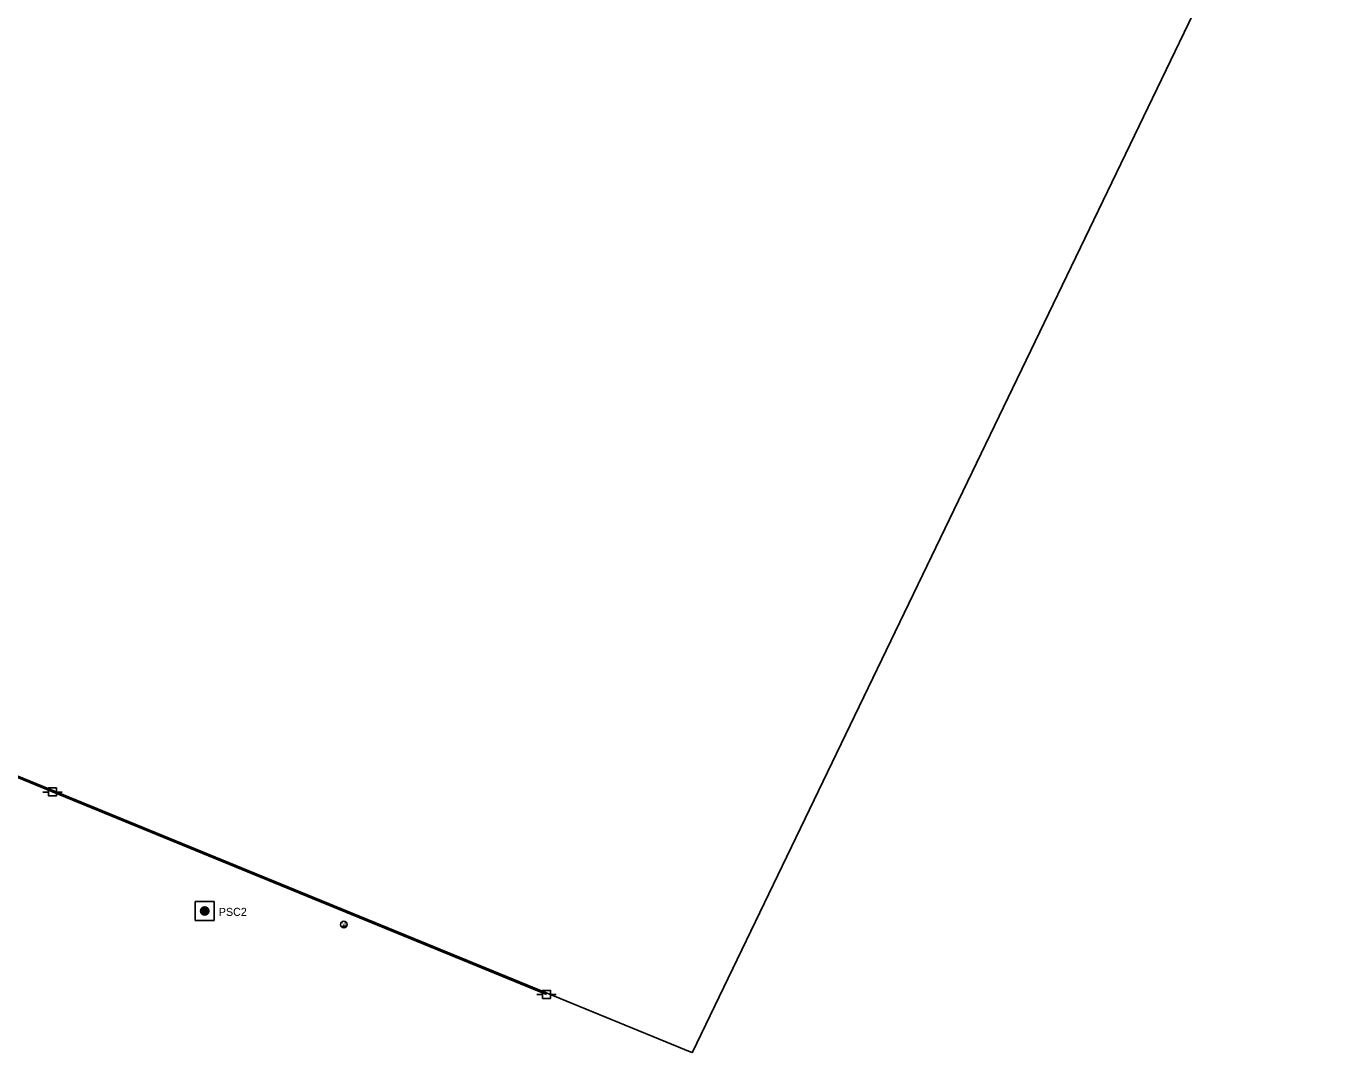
# Model space of a CAD drawing. Extents: x 1903662 to 1907233, y 1108998 to 1112872.
# Drawn here: x 1906248.5 to 1906740.5, y 1109725.4 to 1110110.2 of the extents above; entities that cross this region are included whole.
import ezdxf

# ---------------------------------------------------------------- set-up
doc = ezdxf.new("R2010")
doc.units = 0
for name, color, linetype in [('RD_EX_DV_Prop', 7, 'Continuous'), ('RD_EX_RW', 7, 'Continuous'), ('RD_EX_UT', 7, 'Continuous'), ('RD_HC_Survey', 7, 'Continuous'), ('RD_HC_Survey_txCode', 7, 'Continuous'), ('SV_UT_Electric_Lines', 7, 'Continuous')]:
    doc.layers.add(name, color=color, linetype=linetype)

msp = doc.modelspace()

# ---------------------------------------------------------------- linework, layer by layer
at = {"layer": 'RD_EX_DV_Prop'}
msp.add_lwpolyline([(1906498.14, 1109725.43), (1907232.53, 1111248.36), (1906353.67, 1111725.44)], dxfattribs=at)
at = {"layer": 'RD_EX_RW'}
msp.add_line((1904864.32, 1110395.12), (1906497.97, 1109725.51), dxfattribs=at)
at = {"layer": 'RD_EX_UT'}
for p, q in [((1906254.74, 1109823.13), (1906256.79, 1109823.14)), ((1906258.29, 1109823.17), (1906258.29, 1109823.17)), ((1906259.79, 1109823.14), (1906261.93, 1109823.13)), ((1906367.04, 1109772.92), (1906368.2, 1109772.92)), ((1906439.91, 1109747.27), (1906441.97, 1109747.27)), ((1906443.47, 1109747.31), (1906443.47, 1109747.31)), ((1906444.97, 1109747.27), (1906447.11, 1109747.27))]:
    msp.add_line(p, q, dxfattribs=at)
msp.add_lwpolyline([(1904589.73, 1110482.88), (1904891.43, 1110385.65), (1905171.11, 1110270.76), (1905436.6, 1110161.49), (1905735.85, 1110038.44), (1905992.24, 1109932.67), (1906258.29, 1109823.17), (1906443.47, 1109747.31)], dxfattribs=at)
for points in [[(1906256.79, 1109821.67), (1906256.79, 1109824.67), (1906259.79, 1109824.67), (1906259.79, 1109821.67)], [(1906441.97, 1109745.81), (1906441.97, 1109748.81), (1906444.97, 1109748.81), (1906444.97, 1109745.81)]]:
    msp.add_lwpolyline(points, close=True, dxfattribs=at)
msp.add_circle((1906367.58, 1109773.47), 1.23, dxfattribs=at)
at = {"layer": 'RD_HC_Survey'}
for p, q in [((1906313.89, 1109778.22), (1906313.89, 1109778.95)), ((1906313.94, 1109778.06), (1906313.94, 1109779.11)), ((1906313.99, 1109777.93), (1906313.99, 1109779.23)), ((1906314.04, 1109777.83), (1906314.04, 1109779.33)), ((1906314.09, 1109777.75), (1906314.09, 1109779.42)), ((1906314.14, 1109777.68), (1906314.14, 1109779.49)), ((1906314.19, 1109777.61), (1906314.19, 1109779.56)), ((1906314.24, 1109777.55), (1906314.24, 1109779.62)), ((1906314.29, 1109777.5), (1906314.29, 1109779.67)), ((1906314.34, 1109777.45), (1906314.34, 1109779.72)), ((1906314.39, 1109777.4), (1906314.39, 1109779.76)), ((1906314.44, 1109777.36), (1906314.44, 1109779.81)), ((1906314.49, 1109777.32), (1906314.49, 1109779.84)), ((1906314.54, 1109777.29), (1906314.54, 1109779.88)), ((1906314.59, 1109777.26), (1906314.59, 1109779.91)), ((1906314.64, 1109777.23), (1906314.64, 1109779.94)), ((1906314.69, 1109777.2), (1906314.69, 1109779.97)), ((1906314.74, 1109777.18), (1906314.74, 1109779.99)), ((1906314.79, 1109777.15), (1906314.79, 1109780.01)), ((1906314.84, 1109777.13), (1906314.84, 1109780.03)), ((1906314.89, 1109777.12), (1906314.89, 1109780.05)), ((1906314.94, 1109777.1), (1906314.94, 1109780.07)), ((1906314.99, 1109777.08), (1906314.99, 1109780.08)), ((1906315.04, 1109777.07), (1906315.04, 1109780.1)), ((1906315.09, 1109777.06), (1906315.09, 1109780.11)), ((1906315.14, 1109777.05), (1906315.14, 1109780.12)), ((1906315.19, 1109777.04), (1906315.19, 1109780.12)), ((1906315.24, 1109777.04), (1906315.24, 1109780.13)), ((1906315.29, 1109777.03), (1906315.29, 1109780.13)), ((1906315.34, 1109777.03), (1906315.34, 1109780.14)), ((1906315.39, 1109777.03), (1906315.39, 1109780.14)), ((1906315.44, 1109777.03), (1906315.44, 1109780.14)), ((1906315.49, 1109777.03), (1906315.49, 1109780.14)), ((1906315.54, 1109777.04), (1906315.54, 1109780.13)), ((1906315.59, 1109777.04), (1906315.59, 1109780.13)), ((1906315.64, 1109777.05), (1906315.64, 1109780.12)), ((1906315.69, 1109777.06), (1906315.69, 1109780.11)), ((1906315.74, 1109777.07), (1906315.74, 1109780.1)), ((1906315.79, 1109777.08), (1906315.79, 1109780.09)), ((1906315.84, 1109777.09), (1906315.84, 1109780.08)), ((1906315.89, 1109777.11), (1906315.89, 1109780.06)), ((1906315.94, 1109777.13), (1906315.94, 1109780.04)), ((1906315.99, 1109777.14), (1906315.99, 1109780.02)), ((1906316.04, 1109777.17), (1906316.04, 1109780)), ((1906316.09, 1109777.19), (1906316.09, 1109779.98)), ((1906316.14, 1109777.22), (1906316.14, 1109779.95)), ((1906316.19, 1109777.24), (1906316.19, 1109779.92)), ((1906316.24, 1109777.27), (1906316.24, 1109779.89)), ((1906316.29, 1109777.31), (1906316.29, 1109779.86)), ((1906316.34, 1109777.34), (1906316.34, 1109779.82)), ((1906316.39, 1109777.38), (1906316.39, 1109779.78)), ((1906316.44, 1109777.43), (1906316.44, 1109779.74)), ((1906316.49, 1109777.47), (1906316.49, 1109779.69)), ((1906316.54, 1109777.53), (1906316.54, 1109779.64)), ((1906316.59, 1109777.58), (1906316.59, 1109779.59)), ((1906316.64, 1109777.64), (1906316.64, 1109779.52)), ((1906316.69, 1109777.71), (1906316.69, 1109779.45)), ((1906316.74, 1109777.79), (1906316.74, 1109779.38)), ((1906316.79, 1109777.88), (1906316.79, 1109779.28)), ((1906316.84, 1109777.99), (1906316.84, 1109779.17)), ((1906316.89, 1109778.13), (1906316.89, 1109779.03)), ((1906316.94, 1109778.36), (1906316.94, 1109778.81))]:
    msp.add_line(p, q, dxfattribs=at)
msp.add_lwpolyline([(1906318.93, 1109782.12), (1906311.86, 1109782.12), (1906311.86, 1109775.05), (1906318.93, 1109775.05)], close=True, dxfattribs=at)
msp.add_circle((1906315.4, 1109778.58), 1.55, dxfattribs=at)
at = {"layer": 'SV_UT_Electric_Lines'}
msp.add_lwpolyline([(1904589.73, 1110482.88), (1904891.43, 1110385.65), (1905171.11, 1110270.76), (1905436.6, 1110161.49), (1905735.85, 1110038.44), (1905992.24, 1109932.67), (1906258.29, 1109823.17), (1906443.47, 1109747.31)], dxfattribs=at)

# ---------------------------------------------------------------- texts
at = {"layer": 'RD_EX_UT'}
msp.add_text('W', height=1.5, dxfattribs=at).set_placement((1906366.96, 1109772.97))
at = {"layer": 'RD_HC_Survey_txCode'}
msp.add_text('PSC2', height=3, dxfattribs=at).set_placement((1906320.69, 1109776.73))

doc.saveas('drawing.dxf')
